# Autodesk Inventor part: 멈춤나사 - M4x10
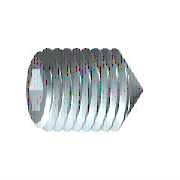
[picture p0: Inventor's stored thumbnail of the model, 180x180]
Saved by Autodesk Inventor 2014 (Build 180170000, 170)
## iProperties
Created: 2012-02
Part Number: 멈춤나사 - M4x10
Material: 강철, 연강
Description: 6각 소켓 머리 없는 멈춤 나사
Document SubType Name: Modeling
Standard: KS B 1028
Designer: mduedu
Standards Organization: KS
Language: ko-KR
Size Designation: 원추점 M4x10
Categories: <MemberInstance><Categories><Category DisplayName="조임쇠" InternalName="e4da775c-781d-43d5-af7c-5136215cf5a6" Mnemonic="FSTN"><Category DisplayName="볼트" InternalN
Density: 1 g/cm^3
Appearance: 강철
Author: mduedu
IsCustomPart: 1
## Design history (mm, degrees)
sketch "스케치1"
  geometry: L1 (0, 0)-(6.833, 0); L2 (10, 1.155)-(10, 2); L3 (10, 2)-(0, 2); L4 (10, 1.155)-(7.5, 1.155); L5 (7.5, 1.155)-(6.833, 0); L6 (0, -0.4)-(0, 2.4) reference; L7 (0, 2)-(0, 0)
  constraints: 13 end point, 3 parallel, 1 collinear, 1 perpendicular, 1 point on line
  dimensions: "d0" = 2.5 distance of L2.start L4.end (= INTI); "d1" = 60 deg angle of L5 L1; "d2" = 4 diameter of L3 L1 (= NND); "d3" = 2.3094 diameter of L4 L1 (= 1.1547 x SW); "d5" = 10 distance from line of L2 L3.end (= NLG)
revolve "본체" sketch "스케치1" stored, may be unused: angle "d6" = 90 deg
sketch "스케치2"
  geometry: L1 (-0.577, 1)-(0.577, 1); L2 (0.577, 1)-(1.155, 0); L3 (1.155, 0)-(0.577, -1); L4 (0.577, -1)-(-0.577, -1); L5 (-0.577, -1)-(-1.155, 0); L6 (-1.155, 0)-(-0.577, 1); 3 further points
  constraints: 12 end point, 1 coincident, 1 horizontal, 13 other
extrude "슬롯" join sketch "스케치2" taper "d7" = 0 deg; stored distance "d21" = 10
workaxis "Work Axis1"
workplane "Work Plane1"
body "Solid1"
feature "스레드" dims "d12" = 10 (= NLG), "d13" = 0
chamfer "모따기1" distance "d8" = 1.8 (computed from NND, SPD, FAWI); stored, may be unused: angle "d9" = 45 deg (= FAWI), second distance "d34" = 1.8 (computed from NND, SPD, FAWI)
chamfer "모따기2" distance "d10" = 0.42941 (= -0.5 x GD1 + 0.5 x NND); stored, may be unused: angle "d11" = 45 deg (= FAWI), second distance "d35" = 0.42941 (= -0.5 x GD1 + 0.5 x NND)
other parameters: "NND" = 4 [user parameter; used in 5 equation terms], "NLG" = 10 [user parameter; used in 2 equation terms], "INTI" = 2.5 [user parameter; used in 1 equation term], "FAWI" = 45 deg [user parameter; used in 4 equation terms], "SW" = 2 [user parameter; used in 2 equation terms], "GD1" = 3.14117 (= THREADDIA - 1.2269 x PTC) [user parameter; used in 2 equation terms], "d4" = 0, "FAWI1" = 45 deg [user parameter], "SPD" = 0.4 [user parameter; used in 2 equation terms], "d36" = 0, "d37" = 0, "GUL" = 0.42941 (= 0.61345 x PTC) [user parameter], "TPU" = 14.28571 (computed from PTC) [user parameter], "TOA" = 30 deg [user parameter], "THREADDIA" = 4 [user parameter; used in 1 equation term], "PTC" = 0.7 [user parameter; used in 4 equation terms], "GAL" = 0.42941 (= 0.61345 x PTC) [user parameter], "E0" = 2.31 (= 1.155 x SW) [user parameter]
